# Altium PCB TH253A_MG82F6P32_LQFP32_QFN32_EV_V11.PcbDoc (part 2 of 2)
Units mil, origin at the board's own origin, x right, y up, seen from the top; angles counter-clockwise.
Board outline 3818.9 x 2637.8 mil, 2 copper layers (Top Layer, Bottom Layer); 102 components, 120 nets, 494 pads, 219 vias.
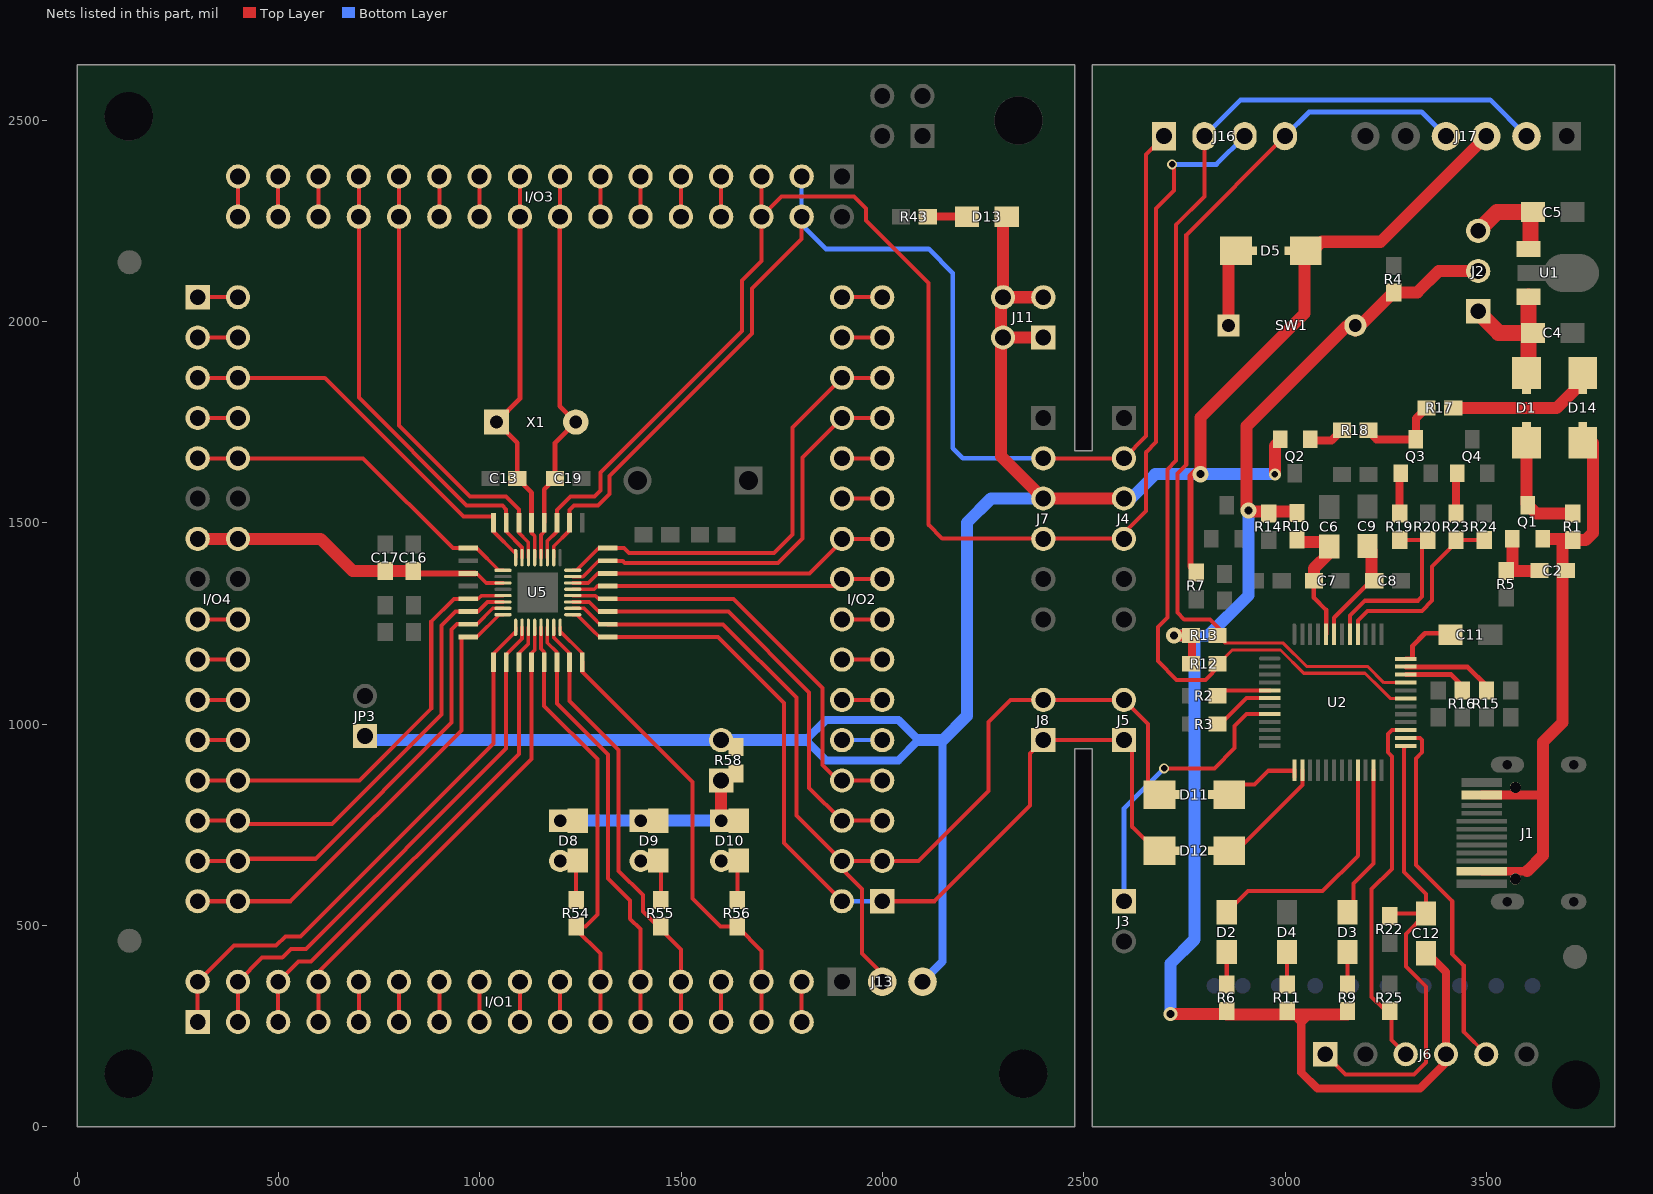
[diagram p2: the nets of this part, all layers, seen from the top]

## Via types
v1: diameter 20, hole 12, Top Layer to Bottom Layer, tented both sides, 164 vias
v2: diameter 30, hole 12, Top Layer to Bottom Layer, tented both sides, 19 vias
v3: diameter 25, hole 16, Top Layer to Bottom Layer, tented both sides, 13 vias
v4: diameter 25, hole 12, Top Layer to Bottom Layer, tented both sides, 7 vias
v5: diameter 40, hole 20, Top Layer to Bottom Layer, tented both sides, 5 vias
v6: diameter 24, hole 12, Top Layer to Bottom Layer, tented both sides, 4 vias
v7: diameter 30, hole 16, Top Layer to Bottom Layer, tented both sides, 3 vias
v8: diameter 50, hole 12, Top Layer to Bottom Layer, tented both sides, 1 vias
v9: diameter 35, hole 20, Top Layer to Bottom Layer, tented both sides, 1 vias
v10: diameter 15, hole 12, Top Layer to Bottom Layer, tented both sides, 1 vias
v11: diameter 60, hole 32, Top Layer to Bottom Layer, tented both sides, 1 vias

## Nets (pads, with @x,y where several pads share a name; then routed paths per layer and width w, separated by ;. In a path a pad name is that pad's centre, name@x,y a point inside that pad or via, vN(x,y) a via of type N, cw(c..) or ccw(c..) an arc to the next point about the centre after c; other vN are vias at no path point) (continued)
ICP/SWD_SCL: J16.2 J17.2 R12.2 U2.31 | length 2959.9
  Top Layer w8: R12.2@2844.45,1160 2868.45,1184 2988.41,1184 3046.41,1126 3198.41,1126 3238.3,1086.1 ; 3238.35,1086.1 3260.72,1063.73 U2.31@3299.91,1063.73
  Top Layer w10: J16.2@2799.45,2485 J16.2@2799.45,2460 2799.45,2310 2729.45,2240 2729.45,1654 2708.2,1632.75 2708.2,1265.05 2684.41,1241.26 2684.41,1156.26 2730.67,1110 2802.45,1110 2837.45,1145 R12.2@2842.45,1150
  Bottom Layer w12: J16.2@2799.45,2460 2889.45,2550 3509.45,2550 J17.2@3599.45,2460
ICP/SWD_SDA: J16.4 J17.4 R13.2 U2.33 | length 2399.4
  Top Layer w8: R13.2@2832.45,1220 2851.45,1201 2995.45,1201 3053.45,1143 3205.45,1143 3245.35,1103.1 U2.33@3299.91,1103.1
  Top Layer w10: R13.2@2842.45,1220 2842.45,1231 2813.45,1260 2749.45,1260 2732.2,1277.25 2732.2,1621.75 2754.45,1644 2754.45,2215 J16.4@2999.45,2460
  Bottom Layer w12: J16.4@2999.45,2460 3059.45,2520 3339.45,2520 J17.4@3399.45,2460
MLINK_RXD: D11.2 I/O2.3 I/O2.4 J5.2 J8.2 J13.2 U5.10 | length 2589.6
  Top Layer w10: U5.10@1317.25,1247.78 1317.48,1247.78 1604.07,1247.78 1786.44,1065.4 1786.44,773.01 I/O2.4@1899.45,660 I/O2.3@1999.45,660 ; I/O2.4@1899.45,640 1909.45,630 ; I/O2.4@1909.45,650 1909.45,630 ; J13.2@1999.45,360 1999.45,380 1949.45,430 1949.45,590 1909.45,630 ; I/O2.3@1999.45,650 I/O2.3@1999.45,660 ; D11.2@2659.45,810 2659.45,825 2659.45,1000 J5.2@2599.45,1060 J8.2@2399.45,1060 2317.55,1060 2263.22,1005.67 2263.22,833.77 2089.45,660 I/O2.3@1999.45,660
MLINK_TXD: D12.1 I/O2.1 I/O2.2 J5.1 J8.1 U5.9 | length 2301.3
  Top Layer w10: U5.9@1317.25,1216.28 1317.48,1216.28 1591.02,1216.28 1754.95,1052.36 1754.95,704.5 I/O2.2@1899.45,560 I/O2.2@1899.45,565 ; I/O2.1@1999.45,560 2129.45,560 2366.78,797.33 2366.78,927.33 J8.1@2399.45,960 J5.1@2599.45,960 J5.1@2605.22,954.23 ; J5.1@2619.45,958 2619.45,745 D12.1@2672.83,691.61
  Bottom Layer w10: I/O2.2@1899.45,560 I/O2.1@1999.45,560
NetC2_2: C2.2 Q1.1 R5.2 | length 170
  Top Layer w30: R5.2@3549.45,1380 R5.2@3564.45,1380 ; Q1.1@3564.45,1465 Q1.1@3564.45,1460 R5.2@3564.45,1380 ; C2.2@3634.45,1380 3631.41,1380 R5.2@3564.45,1380
NetC6_1: C6.1 C7.2 R10.2 U2.44 | length 312.7
  Top Layer w11: C7.2@3071.45,1356.26 3071.45,1313.55 3101.64,1283.36 U2.44@3101.64,1223.13 ; C7.2@3087,1356.26 C7.2@3087,1365.26
  Top Layer w30: R10.2@3044.45,1452 3109.41,1452 C6.1@3109.41,1440.79 ; C7.2@3071.45,1356.26 3071.45,1386.45 C6.1@3108,1423
NetC8_2: C8.2 C9.1 U2.43 | length 261.6
  Top Layer w11: U2.43@3121.33,1223.13 3121.33,1264.18 C8.2@3214.41,1357.26
  Top Layer w30: C9.1@3204.41,1442.05 3214.41,1432.05 C8.2@3214.41,1357.26
NetC11_1: C11.1 U2.36 | length 149.7
  Top Layer w12: U2.36@3299.91,1162.16 3316.61,1162.16 3316.61,1194.68 3347.31,1225.39 C11.1@3404.35,1225.39
NetD1_1: D1.1 Q1.3 R1.2 | length 276.4
  Top Layer w30: D1.1@3599.41,1698.39 3599.41,1546.98 Q1.3@3602.45,1543.94 3623.38,1523 R1.2@3714.45,1523
NetD2_1: D2.1 R6.2 | length 97
  Top Layer w10: R6.2@2855,345 R6.2@2855,353.26 D2.1@2855,434.05 D2.1@2855,442
NetD3_1: D3.1 R9.2 | length 97
  Top Layer w10: R9.2@3155,345 R9.2@3155,353.26 D3.1@3155,434.05 D3.1@3155,442
NetD4_1: D4.1 R11.2 | length 97
  Top Layer w10: R11.2@3005,345 R11.2@3005,353.26 D4.1@3005,434.05 D4.1@3005,442
NetD5_1: D5.1 SW1.1 | length 215.1
  Top Layer w20: D5.1@2860.28,2175 D5.1@2877.8,2175 D5.1@2911.26,2175
  Top Layer w30: SW1.1@2859.49,1990 D5.1@2859.49,2154.13
NetD8_1: D8.1 D9.1 D10.1 R58.1 | length 500
  Top Layer w30: D10.1@1599.45,760 R58.1@1599.45,860
  Bottom Layer w30: D8.1@1199.45,760 D9.1@1399.45,760 D10.1@1599.45,760
NetD8_2: D8.2 R54.2 | length 94.8
  Top Layer w10: R54.2@1239.45,563 D8.2@1239.45,657.76
NetD9_2: D9.2 R55.2 | length 92.1
  Top Layer w10: R55.2@1449.45,563 D9.2@1449.45,655.13
NetD10_2: D10.2 R56.2 | length 94.8
  Top Layer w10: R56.2@1639.45,563 D10.2@1639.45,657.76
NetD11_1: D11.1 U2.13 | length 209.6
  Top Layer w10: D11.1@2846.06,810 D11.1@2861.06,825 D11.1@2876.06,840 ; D11.1@2884.45,850 2924.45,850 2958.51,884.06 U2.13@3020.37,884.06 ; U2.13@3022.9,868.45 U2.13@3022.9,885.65
NetD12_2: D12.2 U2.14 | length 287
  Top Layer w10: D12.2@2854.45,700 2861.06,700 2894.45,700 3042.59,848.14 U2.14@3042.59,885.65
NetD13_2: D13.2 R43.2 | length 90
  Top Layer w20: R43.2@2129.45,2260 D13.2@2210.24,2260
  Top Layer w30: D13.2@2210.24,2260 D13.2@2219.45,2260
NetD14_2: D14.2 R17.1 | length 348.7
  Top Layer w30: R17.1@3417.41,1785 3669.41,1785 ; 3674.41,1785 D14.2@3733.48,1844.07 ; D14.2@3722.56,1868.15 D14.2@3734.41,1868.15 ; D14.2@3728.48,1844.07 D14.2@3729.41,1845
NetI/O1_9: I/O1.9 I/O1.10 | length 100
  Top Layer w10: I/O1.9@699.45,260 I/O1.10@699.45,360
NetI/O1_11: I/O1.11 I/O1.12 | length 100
  Top Layer w10: I/O1.11@799.45,260 I/O1.12@799.45,360
NetI/O1_13: I/O1.13 I/O1.14 | length 100
  Top Layer w10: I/O1.13@899.45,260 I/O1.14@899.45,360
NetI/O1_15: I/O1.15 I/O1.16 | length 100
  Top Layer w10: I/O1.15@999.45,260 I/O1.16@999.45,360
NetI/O1_17: I/O1.17 I/O1.18 | length 116.7
  Top Layer w10: I/O1.18@1087.63,371.82 I/O1.18@1099.45,360 I/O1.17@1099.45,260
NetI/O1_19: I/O1.19 I/O1.20 | length 100
  Top Layer w10: I/O1.19@1199.45,260 I/O1.20@1199.45,360
NetI/O1_27: I/O1.27 I/O1.28 | length 112.4
  Top Layer w10: I/O1.28@1595.19,360 1595.19,355.74 I/O1.28@1599.45,351.48 ; I/O1.27@1599.45,260 I/O1.28@1599.45,351.48 ; I/O1.28@1599.45,360 I/O1.28@1599.45,351.48 ; I/O1.28@1600.93,350 I/O1.28@1599.45,351.48
NetI/O1_31: I/O1.31 I/O1.32 | length 100
  Top Layer w10: I/O1.31@1799.45,260 I/O1.32@1799.45,360
NetI/O2_9: I/O2.9 I/O2.10 | length 100
  Bottom Layer w10: I/O2.10@1899.45,960 I/O2.9@1999.45,960
NetI/O2_11: I/O2.11 I/O2.12 | length 100
  Top Layer w10: I/O2.12@1899.45,1060 I/O2.11@1999.45,1060
NetI/O2_13: I/O2.13 I/O2.14 | length 100
  Top Layer w10: I/O2.14@1899.45,1160 I/O2.13@1999.45,1160
NetI/O2_15: I/O2.15 I/O2.16 | length 100
  Top Layer w10: I/O2.16@1899.45,1260 I/O2.15@1999.45,1260
NetI/O2_21: I/O2.21 I/O2.22 | length 100
  Top Layer w10: I/O2.22@1899.45,1560 I/O2.21@1999.45,1560
NetI/O2_23: I/O2.23 I/O2.24 | length 100
  Top Layer w10: I/O2.24@1899.45,1660 I/O2.23@1999.45,1660
NetI/O2_29: I/O2.29 I/O2.30 | length 100
  Top Layer w10: I/O2.30@1899.45,1960 I/O2.29@1999.45,1960
NetI/O2_31: I/O2.31 I/O2.32 | length 100
  Top Layer w10: I/O2.32@1899.45,2060 I/O2.31@1999.45,2060
NetI/O3_7: I/O3.7 I/O3.8 | length 100
  Top Layer w10: I/O3.8@1599.45,2260 I/O3.7@1599.45,2360
NetI/O3_9: I/O3.9 I/O3.10 | length 100
  Top Layer w10: I/O3.10@1499.45,2260 I/O3.9@1499.45,2360
NetI/O3_11: I/O3.11 I/O3.12 | length 100
  Top Layer w10: I/O3.12@1399.45,2260 I/O3.11@1399.45,2360
NetI/O3_13: I/O3.13 I/O3.14 | length 100
  Top Layer w10: I/O3.14@1299.45,2260 I/O3.13@1299.45,2360
NetI/O3_19: I/O3.19 I/O3.20 | length 100
  Top Layer w10: I/O3.20@999.45,2260 I/O3.19@999.45,2360
NetI/O3_21: I/O3.21 I/O3.22 | length 100
  Top Layer w10: I/O3.22@899.45,2260 I/O3.21@899.45,2360
NetI/O3_27: I/O3.27 I/O3.28 | length 100
  Top Layer w10: I/O3.28@599.45,2260 I/O3.27@599.45,2360
NetI/O3_29: I/O3.29 I/O3.30 | length 100
  Top Layer w10: I/O3.30@499.45,2260 I/O3.29@499.45,2360
NetI/O3_31: I/O3.31 I/O3.32 | length 100
  Top Layer w10: I/O3.32@399.45,2260 I/O3.31@399.45,2360
NetI/O4_1: I/O4.1 I/O4.2 | length 123.5
  Top Layer w10: I/O4.1@299.45,2060 I/O4.2@399.45,2060 I/O4.2@399.45,2036.48
NetI/O4_3: I/O4.3 I/O4.4 | length 100
  Top Layer w10: I/O4.3@299.45,1960 I/O4.4@399.45,1960
NetI/O4_7: I/O4.7 I/O4.8 | length 100
  Top Layer w10: I/O4.7@299.45,1760 I/O4.8@399.45,1760
NetI/O4_17: I/O4.17 I/O4.18 | length 100
  Top Layer w10: I/O4.17@299.45,1260 I/O4.18@399.45,1260
NetI/O4_19: I/O4.19 I/O4.20 | length 100
  Top Layer w10: I/O4.19@299.45,1160 I/O4.20@399.45,1160
NetI/O4_21: I/O4.21 I/O4.22 | length 100
  Top Layer w10: I/O4.21@299.45,1060 I/O4.22@399.45,1060
NetI/O4_23: I/O4.23 I/O4.24 | length 100
  Top Layer w10: I/O4.23@299.45,960 I/O4.24@399.45,960
NetQ2_1: Q2.1 R18.2 | length 89.8
  Top Layer w20: Q2.1@3062.41,1703.94 3115.38,1703.94 R18.2@3141.45,1730
NetQ3_1: Q3.1 R19.2 | length 117.1
  Top Layer w20: R19.2@3284.45,1540.04 R19.2@3284.45,1523 Q3.1@3284.45,1620.53 ; Q3.1@3286.95,1620.53 Q3.1@3286.95,1623.03
NetQ3_2: Q3.2 R17.2 R18.1 | length 192.7
  Top Layer w20: R18.1@3212.45,1730 3212.45,1721.96 3227.44,1706.97 Q3.2@3324.95,1706.97 ; 3324.95,1730 3324.95,1758.54 R17.2@3351.41,1785
NetQ4_1: Q4.1 R23.2 | length 100
  Top Layer w20: R23.2@3424.45,1523 Q4.1@3424.45,1620.53 ; Q4.1@3426.95,1620.53 Q4.1@3426.95,1623.03
NetR15_1: R15.1 U2.35 | length 263.6
  Top Layer w12: U2.35@3299.91,1141.47 3329.45,1141.47 ; 3361.71,1141.47 3329.45,1141.47 ; R15.1@3500,1083 3500,1095 3453.53,1141.47 3329.45,1141.47
NetR16_1: R16.1 U2.34 | length 163.6
  Top Layer w12: U2.34@3299.91,1122.79 3412.21,1122.79 3440,1095 R16.1@3440,1083
OCD_CLK/P44: I/O3.3 I/O3.4 J4.2 J7.2 J16.1 U5.18 | length 3313.6
  Top Layer w10: U5.18@1222.99,1498 U5.18@1222.99,1500 1222.99,1531.88 1234.11,1543 1294.11,1543 1322,1570.89 1322,1616.07 1675.93,1970 1675.93,2081.48 1799.45,2205 I/O3.4@1799.45,2260 ; J7.2@2399.45,1659 J4.2@2599.45,1659 ; J4.2@2599.45,1660 2654.45,1715 2654.45,2415 J16.1@2699.45,2460
  Bottom Layer w10: I/O3.4@1799.45,2240 I/O3.4@1799.45,2260 I/O3.3@1799.45,2360
  Bottom Layer w12: I/O3.4@1799.45,2240 1859.45,2180 2114.45,2180 2174.45,2120 2174.45,1685 2199.45,1660 J7.2@2399.45,1660 J7.2@2384.45,1675
OCD_SDA/P45: I/O3.5 I/O3.6 J4.4 J7.4 J16.3 U5.19 | length 3920.1
  Top Layer w10: U5.19@1191.5,1500 1191.5,1531.5 1225,1565 1285,1565 1300,1580 1300,1625.18 1650.93,1976.11 1650.93,2101.48 1699.45,2150 I/O3.6@1699.45,2260 ; I/O3.5@1699.45,2360 I/O3.6@1699.45,2260 ; J7.4@2399.45,1460 2398.45,1461 2148.45,1461 2114.45,1495 2114.45,2095 1959.45,2250 1959.45,2280 1929.45,2310 1749.45,2310 I/O3.6@1699.45,2260 ; J7.4@2399.45,1461 J4.4@2585.45,1461 ; J4.4@2592.45,1467 2654.45,1529 2654.45,1675 2679.45,1700 2679.45,2280 2724.45,2325 v3@2724.45,2390
  Bottom Layer w12: v3(2719.45,2390) 2829.45,2390 J16.3@2899.45,2460
P01: I/O3.23 I/O3.24 U5.22 | length 1040.2
  Top Layer w10: I/O3.23@799.45,2360 I/O3.24@799.45,2260 799.45,1741.8 976.25,1565 1065,1565 1097.01,1532.99 U5.22@1097.01,1500 U5.22@1097.01,1495
P02: I/O3.25 I/O3.26 U5.23 | length 1065.6
  Top Layer w10: I/O3.25@699.45,2360 I/O3.26@699.45,2260 699.45,1810.69 967.14,1543 1055.89,1543 1065.51,1533.38 U5.23@1065.51,1500 U5.23@1065.51,1498
P05: I/O4.5 I/O4.6 U5.24 | length 892.6
  Top Layer w10: I/O4.5@299.45,1860 I/O4.6@399.45,1860 ; I/O4.6@409.45,1850 I/O4.6@399.45,1860 ; U5.24@1035,1515 1034.02,1515 960,1515 615,1860 I/O4.6@399.45,1860
P07: I/O4.9 I/O4.10 U5.25 | length 763.9
  Top Layer w10: I/O4.9@299.45,1660 I/O4.10@399.45,1660 710,1660 932.99,1437.01 U5.25@971.02,1437.01
P10: I/O4.25 I/O4.26 U5.29 | length 984.9
  Top Layer w10: I/O4.25@299.45,860 I/O4.26@399.45,860 700.93,860 879.45,1038.52 879.45,1254.45 936.02,1311.02 U5.29@971.02,1311.02
P11: I/O4.27 I/O4.28 U5.30 | length 1033
  Top Layer w10: I/O4.27@299.45,760 I/O4.28@399.45,760 ; I/O4.28@389.45,760 I/O4.28@399.45,760 ; U5.30@971.02,1279.53 939.53,1279.53 904.45,1244.45 904.45,1023.52 632.69,751.76 407.69,751.76 I/O4.28@399.45,760
P12: I/O4.29 I/O4.30 U5.31 | length 1050.4
  Top Layer w10: I/O4.29@299.45,660 I/O4.30@399.45,660 404.94,665.49 591.42,665.49 929.45,1003.52 929.45,1234.45 943.03,1248.03 U5.31@971.02,1248.03
P13: I/O4.31 I/O4.32 U5.32 | length 1061.9
  Top Layer w10: I/O4.31@299.45,560 I/O4.32@399.45,560 530.47,560 955,984.53 U5.32@955,1215
P14: I/O1.1 I/O1.2 U5.1 | length 1281.3
  Top Layer w10: I/O1.1@299.45,260 I/O1.2@299.45,360 389.45,450 494.45,450 517.44,472.99 555,472.99 1034.02,952.01 U5.1@1034.02,1153.54
P15: I/O1.3 I/O1.4 U5.2 | length 1220.5
  Top Layer w10: I/O1.3@399.45,260 I/O1.4@399.45,360 459.45,420 509.45,420 530.94,441.5 568.04,441.5 1065.51,938.97 U5.2@1065.51,1153.54
P16: I/O1.5 I/O1.6 U5.3 | length 1159.6
  Top Layer w10: I/O1.5@499.45,260 I/O1.6@499.45,360 549.45,410 581.09,410 1097.01,925.92 U5.3@1097.01,1153.54
P17: I/O1.7 I/O1.8 U5.4 | length 1112.7
  Top Layer w10: I/O1.7@599.45,260 I/O1.8@599.45,360 599.45,383.82 1128.5,912.87 U5.4@1128.5,1153.54
P22: I/O1.21 I/O1.22 R54.1 U5.5 | length 998.1
  Top Layer w10: U5.5@1160,1153.54 1160,1045.06 1292.01,913.05 1292.01,527.01 1262,497 R54.1@1239.45,497 1239.45,490 1299.45,430 I/O1.22@1299.45,370 ; I/O1.21@1299.45,260 I/O1.22@1299.45,360
P23: I/O1.23 I/O1.24 U5.6 | length 989.6
  Top Layer w10: U5.6@1191.5,1153.54 1191.5,1051.03 1318.5,924.03 1318.5,616.95 1373.5,561.95 1373.5,516.5 1399.35,490.65 1399.35,360 I/O1.24@1399.35,350 ; I/O1.23@1399.45,260 I/O1.24@1399.45,360
P24: I/O1.25 I/O1.26 R55.1 U5.7 | length 1041.1
  Top Layer w9: 1222.99,1122.01 U5.7@1222.99,1153.54
  Top Layer w10: U5.7@1222.99,1150 1222.99,1057.01 1345,935 1345,635 1405,575 1405,534.45 1445.95,493.5 R55.1@1449.45,490 ; R55.1@1449.45,497 R55.1@1449.45,490 ; I/O1.25@1499.45,260 I/O1.26@1499.45,360 ; I/O1.26@1499.45,361.9 1499.45,440 R55.1@1449.45,490
P26: I/O1.29 I/O1.30 R56.1 U5.8 | length 1102.5
  Top Layer w10: U5.8@1254.35,1130 U5.8@1254.49,1129.86 ; U5.8@1254.49,1153.54 U5.8@1254.49,1129.86 ; 1528.1,856.25 U5.8@1254.49,1129.86 ; 1528.24,856.11 1528.24,566.21 1576.62,517.82 1597.45,497 R56.1@1639.45,497 1699.45,437 I/O1.30@1699.45,360 I/O1.29@1699.45,260
P32: I/O2.5 I/O2.6 U5.11 | length 1036.1
  Top Layer w10: U5.11@1317.25,1279.28 1317.48,1279.28 1617.11,1279.28 1817.94,1078.45 1817.94,841.51 I/O2.6@1899.45,760 I/O2.5@1999.45,760
P33: I/O2.7 I/O2.8 U5.12 | length 981.1
  Top Layer w10: U5.12@1317.25,1310.77 1317.48,1310.77 1630.16,1310.77 1850.93,1090 1850.93,898.52 1889.45,860 I/O2.8@1899.45,860 I/O2.7@1999.45,860
P34: I/O2.17 I/O2.18 U5.13 | length 713.7
  Top Layer w10: 1292.96,1342.52 U5.13@1317.48,1342.52 1892.52,1342.52 1904.72,1354.72 1910,1360 I/O2.17@1999.45,1360
P35: I/O2.19 I/O2.20 U5.14 | length 729.4
  Top Layer w10: U5.14@1317.48,1374.02 1818.46,1374.02 1896.95,1452.5 1899.45,1452.5 1906.95,1452.5 I/O2.20@1912.2,1457.76 ; I/O2.20@1899.45,1460 I/O2.19@1999.45,1460
P40: I/O2.25 I/O2.26 U5.15 | length 943.7
  Top Layer w10: U5.15@1325,1405 1355,1405 1360,1400 1740.93,1400 1801.18,1460.25 1801.18,1661.73 I/O2.26@1899.45,1760 I/O2.25@1999.45,1760
P41: I/O2.27 I/O2.28 U5.16 | length 1036.9
  Top Layer w10: U5.16@1317.48,1437.01 1357.99,1437.01 1370,1425 1730.93,1425 1776.43,1470.5 1776.43,1736.98 I/O2.28@1899.45,1860 ; I/O2.28@1885.82,1860 I/O2.28@1899.45,1860 ; I/O2.27@1999.45,1860 I/O2.28@1899.45,1860
P44: J6.5 U2.26 | length 900.8
  Top Layer w10: U2.26@3299.91,965.31 3334.69,965.31 3340,960 3340,930 3325,915 3325,650 3415,560 3415,429 3443.55,400.45 3443.55,235.9 J6.5@3499.45,180
P45: J6.3 R25.1 U2.27 | length 924.9
  Top Layer w10: R25.1@3263.72,290.72 3263.72,287 3263.72,215.72 J6.3@3299.45,180 ; R25.1@3265,292 3260,292 3245.44,292 3215,322.44 3215,590 3265,640 3265,920 3255,930 3255,975 3264.99,984.99 U2.27@3299.91,984.99 ; J6.3@3300.72,181.28 J6.3@3308,174
PASS: D3.2 U2.23 | length 376.3
  Top Layer w10: D3.2@3170,530 3170,532.47 3170,604.16 3219.75,653.92 U2.23@3219.75,885.65
RST: C12.2 J6.1 R22.2 U2.25 | length 1228.1
  Top Layer w10: J6.1@3099.45,180 3149.45,130 3320,130 3350,160 3350,348 3300,398 3300,479.21 C12.2@3350,529.21 ; R22.2@3266.21,529.21 C12.2@3350,529.21 ; U2.25@3300,945 3295,940 3295,633 3350,578 C12.2@3350,529.21 ; U2.25@3309.45,945.62 U2.25@3318.83,945.62
RST_CTRL_51: R19.1 R20.1 U2.41 | length 455
  Top Layer w10: U2.41@3160.7,1223.13 3160.7,1269.12 3197.83,1306.26 3329.41,1306.26 3339.45,1316.3 R20.1@3339.45,1457 ; R19.1@3284.45,1457 R20.1@3339.45,1457 ; R20.1@3354.45,1457 R20.1@3339.45,1457
RST_CTRL_ARM: R23.1 R24.1 U2.40 | length 474.6
  Top Layer w10: U2.40@3180.38,1223.13 3180.38,1256.93 3204.71,1281.26 3339.41,1281.26 3364.45,1306.3 3364.45,1391.3 R23.1@3421.91,1448.76 ; R23.1@3424.45,1457 R24.1@3494.45,1457
TOOL_OPTION0: R2.1 U2.5 | length 135.2
  Top Layer w10: R2.1@2832.45,1070 2846.37,1083.92 U2.5@2961.93,1083.92
TOOL_OPTION1: R3.1 U2.6 | length 156.1
  Top Layer w10: R3.1@2832.45,1000 2839.45,1000 2903.68,1064.23 U2.6@2961.93,1064.23
USBOK: D2.2 U2.21 | length 596.3
  Top Layer w10: D2.2@2855,532.47 2907.53,585 3092.45,585 3180.38,672.94 U2.21@3180.38,885.65
VCAP: C16.1 C17.1 I/O4.13 I/O4.14 U5.27 | length 768.9
  Top Layer w15: C16.1@835,1374.02 U5.27@971.02,1374.02 U5.27@987.76,1374.02
  Top Layer w30: I/O4.13@299.45,1460 I/O4.14@399.45,1460 604.45,1460 642.22,1422.22 ; 620,1444.45 642.22,1422.22 ; 805.98,1380 790,1380 ; C16.1@835,1380 790,1380 ; 642.22,1422.22 684.45,1380 C17.1@765,1380 790,1380
VCC_USB: C2.1 D14.1 J1.A4 J1.A9 J1.M5 J1.M6 Q1.2 R1.1 | length 1456.2
  Top Layer w22: J1.A4@3488.25,634.61 3571.65,634.61 3601.07,634.61 ; J1.A9@3488.25,823.62 3571.65,823.62 3640,823.62
  Top Layer w30: 3601.07,634.61 3640,673.54 3640,823.62 3640,955 3689.33,1004.33 3689.33,1381.26 3689.33,1446.88 ; Q1.2@3639.45,1460 3691.45,1460 ; R1.1@3704.45,1457 R1.1@3714.45,1457 3746.41,1457 3764.41,1475 D14.1@3764.41,1698.39
VCP_OPTION: J3.1 U2.8 | length 722
  Top Layer w10: v3(2699.41,890) 2824.45,890 2874.45,940 2874.45,995 2904.31,1024.86 U2.8@2961.93,1024.86
  Bottom Layer w12: J3.1@2599.45,560 2599.45,790.04 v3(2699.41,890)
VDD: C12.1 J2.2 J6.4 R4.1 R6.1 R9.1 R10.1 R11.1 R12.1 R13.1 R14.2 SW1.2 | length 3958.9
  Top Layer w12: R11.1@3014.19,279.52 3014.71,279 3040,253.71 3040.35,253.36 ; 3040.36,251.65 3066.52,277.81
  Top Layer w20: v5@2727.52,1215 R13.1@2761.45,1215 ; v5@2732.52,1225 R13.1@2766.45,1225 ; R12.1@2768.45,1150 R13.1@2768.45,1219.56 ; 3040,279 3040,253.71 3040,135 3080,95 3335,95 3399.45,159.45 J6.4@3399.45,180 3399.45,384.55 3360,424 C12.1@3360,430.79
  Top Layer w30: v9(2715,280) R6.1@2855,280 ; R6.1@2855,279 3005,279 3014.71,279 3040,279 R9.1@3155,279 ; R14.2@2964.41,1528 2959.41,1528 2911.41,1528 v5(2909.41,1530) 2904.41,1535 2904.41,1740 3153.16,1988.75 3163.24,1988.75 3168.22,1983.77 3174.45,1977.54 3180.68,1983.77 3268.91,2072 R4.1@3269.45,2072 3328.41,2072 3381.41,2125 J2.2@3479.45,2125 ; R14.2@2969.41,1528 R10.1@3029.41,1528
  Bottom Layer w30: v9(2715,280) 2715,405 2775,465 2775,1220 ; v5(2724.45,1220) 2775,1220 ; 2775,1220.1 2775,1220 ; v5(2909.41,1530) 2909.41,1319.96 2809.45,1220 2775,1220
VDD3: C5.1 J2.3 U1.1 | length 231.2
  Top Layer w40: J2.3@3479.45,2225 3525.71,2271.26 C5.1@3609.41,2271.26 ; U1.1@3609.41,2195 C5.1@3609.41,2271.26 ; C5.1@3615.2,2271.26 C5.1@3609.41,2271.26
VDD5: C4.1 D1.2 J2.1 U1.3 | length 318.5
  Top Layer w40: J2.1@3477.97,2023.52 3530.24,1971.26 C4.1@3604.41,1971.26 ; D1.2@3604.41,1901.61 C4.1@3604.41,1971.26 ; U1.3@3604.41,2061.26 C4.1@3604.41,1971.26 ; C4.1@3615.2,1971.26 C4.1@3604.41,1971.26
VDUT: D5.2 D13.1 J4.3 J7.3 J11.1 J11.2 J11.3 J11.4 J13.3 J17.3 JP3.1 Q2.2 R7.1 R58.2 | length 6571.2
  Top Layer w15: R7.1@2779.45,1376 2764.45,1391 2764.45,1615.5 2779.45,1630.5 2789.45,1640.5 ; v5@2797.2,1612.75 v5@2799.45,1615
  Top Layer w20: D5.2@3017.56,2175 D5.2@3051.02,2175 D5.2@3068.54,2175
  Top Layer w30: J11.4@2294.45,2060 2294.45,1960 2294.45,1665 J7.3@2399.45,1560 J4.3@2599.45,1560 ; J11.2@2299.45,1960 J11.1@2399.45,1960 ; J11.4@2299.45,2060 D13.1@2299.45,2250.79 ; J11.4@2309.45,2060 J11.3@2399.45,2060 J11.3@2409.45,2060 ; v5(2789.45,1620.5) 2789.45,1640.5 2789.45,1760.91 3048.54,2020 D5.2@3048.54,2170 ; v7@2974.41,1620.5 2974.41,1690.94 Q2.2@2987.41,1703.94 ; D5.2@3063.54,2170 3068.54,2175 3091.3,2197.76 3237.21,2197.76 J17.3@3499.45,2460
  Bottom Layer w20: J13.3@2099.45,360 2149.45,410 2149.45,960 ; 1809.45,960 1859.45,1010 2039.45,1010 2089.45,960 2039.45,910 1859.45,910 1809.45,960
  Bottom Layer w30: JP3.1@715,960 1120,960 ; 899.45,960 1120,960 ; 1809.45,960 R58.2@1599.45,960 1120,960 ; 2089.45,960 2149.45,960 2209.45,1020 2209.45,1500 2269.45,1560 J7.3@2399.45,1560 ; J4.3@2617.48,1560.5 2677.48,1620.5 v5(2789.45,1620.5) v7@2974.41,1620.5
  other v7: 2974.41,1620
XIN/P61: C19.1 I/O3.15 I/O3.16 U5.20 X1.2 | length 910.7
  Top Layer w10: I/O3.16@1199.45,2260 I/O3.15@1199.45,2360
  Top Layer w12: U5.20@1160,1500 1160,1583 C19.1@1187,1610 1187,1698.58 X1.2@1238.43,1750 1198.74,1789.68 1198.74,2260 I/O3.16@1198.74,2261.79
XOUT/P60: C13.1 I/O3.17 I/O3.18 U5.21 X1.1 | length 920
  Top Layer w10: I/O3.18@1099.45,2260 I/O3.17@1099.45,2360
  Top Layer w12: I/O3.18@1099.45,2260 1099.45,1807.87 X1.1@1041.58,1750 1093,1698.58 C13.1@1093,1610 1128.5,1574.5 U5.21@1128.5,1500
pads on no net: J1.A5 J1.A8 J1.B5 J1.B8 J6.6 J7.1 U2.1 U2.2 U2.3 U2.4 U2.7 U2.24 U2.28 U2.29 U2.30 U2.32 U2.37 U2.38 U2.39 U2.46

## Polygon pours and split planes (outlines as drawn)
GND_POWER on Bottom Layer "Top Layer-No Net" (hatched 90Degree grid 10 track 10, remove dead copper, pour order 1001): 29.45,30 3789.45,30 3789.45,2610 29.45,2610
GND_POWER on Top Layer "Top Layer-No Net" (hatched 90Degree grid 10 track 10, remove dead copper, pour order 1001): 29.45,30 3789.45,30 3789.45,2610 29.45,2610

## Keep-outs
Top Layer:
  circle w5: c130,2146.9 r59.06
  circle w5: c130,461.9 r59.06
  circle w5: c3720,421.9 r59.06
Keep-Out Layer:
  lines w7.88: 27.88,201.48 cw(c128.35,131.26) 205.29,35.84 ; 32.93,2432.11 ccw(c128.35,2509.06) 198.57,2609.52 ; 2260.85,2594.47 ccw(c2337.8,2499.06) 2438.26,2428.83 ; 2279.23,30.79 cw(c2349.45,131.26) 2444.87,208.2
  lines w15: 3818.9,1.26 3818.9,2639.06

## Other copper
Top Layer:
  pour cut-out: 2439.45,2639.06 2559.45,2639.06 2559.45,0 2439.45,0
Bottom Layer:
  pour cut-out: 2439.45,2639.06 2559.45,2639.06 2559.45,0 2439.45,0

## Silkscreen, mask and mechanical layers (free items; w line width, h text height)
Top Overlay:
  circle w5: c2337.8,2499.06 r120
  circle w5: c2349.45,131.26 r120
  circle w5: c128.35,131.26 r120
  circle w5: c128.35,2509.06 r120
  region: 2601.52,264.05 2627.17,335.95 2611.52,334.05 2611.52,394.05 2591.52,394.05 2591.52,334.05 2577.17,335.95
  region: 1999.45,450 2009.45,450 2009.45,420 2019.45,420 2004.45,405 1989.45,420 1999.45,420
  text "GND" at 1789.45,2560 h50
  text "P02" at 724.45,2425 h40 r90
  text "P01" at 824.45,2425 h40 r90
  text "P60" at 1070,2425 h40 r90
  text "X_OUT" at 1120,2425 h40 r90
  text "P61" at 1205,2425 h40 r90
  text "X_IN" at 1255,2425 h40 r90
  text "P45" at 1724.45,2425 h40 r90
  text "P44" at 1824.45,2425 h40 r90
  text "RST" at 1924.45,2425 h40 r90
  text "When J16 Open," at 2564.45,2335 h45
  text "Power" at 2149.45,2320 h50
  text "SCL" at 3619.45,2320 h35 r90
  text "CLK" at 3719.45,2320 h35 r90
  text "RST" at 3219.45,2310 h37 r90
  text "GND" at 3319.45,2305 h37 r90
  text "SDA" at 3419.45,2305 h37 r90
  text "VCC" at 3519.45,2305 h37 r90
  text "SW1 must be off." at 2564.45,2260 h45
  text "VDD3" at 3289.41,2201.9 h37
  text "VDUT" at 2249.45,2130 h50
  text "VDD" at 3319.45,2105 h37
  text "VDD5" at 3289.41,1991.9 h37
  text "2024.02" at 1439.45,1990 h40
  text "TH253A" at 479.45,1980 h60
  text "MG82F6P32_LQFP32_QFN32_EV_V11" at 489.45,1890 h50
  text "Power On" at 3099.45,1845 h45
  text "P05" at 129.45,1840 h40
  text "P41" at 2059.45,1840 h40
  text "Power Off" at 2669.45,1840 h45
  text "P40" at 2059.45,1740 h40
  text "RESET" at 1419.45,1720 h50
  text "P07" at 129.45,1640 h40
  text "SCL" at 2239.45,1640 h35
  text "GND" at 129.45,1540 h40
  text "VDUT" at 2209.45,1540 h35
  text "Vcap" at 104.45,1440 h40
  text "P35" at 2059.45,1440 h40
  text "SDA" at 2239.45,1440 h35
  text "VDD" at 129.45,1340 h40
  text "P34" at 2059.45,1340 h40
  text "GND" at 2239.45,1340 h35
  text "RST" at 2239.45,1240 h35
  text "↓" at 2329.45,1090 h110 r90
  text "↓" at 2719.45,1060 h100 r90
  text "P31_TX" at 2139.45,1040 h37
  text "↓" at 2669.45,960 h100 r270
  text "P30_RX" at 2139.45,950 h37
  text "↓" at 2279.45,930 h110 r270
  text "U5 current" at 580.93,865 h45 r90
  text "measurement" at 640.93,860 h40 r90
  text "P10" at 129.45,840 h40
  text "P33" at 2059.45,840 h40
  text "P11" at 129.45,740 h40
  text "P32" at 2059.45,740 h40
  text "P12" at 129.45,640 h40
  text "P31" at 2059.45,640 h40
  text "P13" at 129.45,540 h40
  text "P30" at 2059.45,540 h40
  text "P31_TX" at 1929.45,460 h37
  text "GND" at 1859.45,410 h35
  text "VDD" at 2099.45,410 h35
  text "ISP" at 2169.45,310 h50
  text "J3" at 2559.45,201.9 h45
  text "Open Disable VCP." at 2540,130 h40
  text "P14" at 324.45,100 h40 r90
  text "P15" at 424.45,100 h40 r90
  text "P16" at 524.45,100 h40 r90
  text "P17" at 624.45,100 h40 r90
  text "P22" at 1324.45,100 h40 r90
  text "P23" at 1424.45,100 h40 r90
  text "P24" at 1524.45,100 h40 r90
  text "P26" at 1719.45,100 h40 r90
  text "Short Enable VCP." at 2540,35 h40
Mechanical 1:
  circle w7.88: c2499.45,1615 r27
  circle w7.88: c2499.45,1505 r27
  circle w7.88: c2499.45,1418 r25
  circle w7.88: c2499.45,1300 r25
  circle w7.88: c2499.45,1010 r33
  lines w7.88: 2477.8,1080 2477.8,1234 2521.1,1234 2521.1,1080 2477.8,1080
  lines w8.88: 0,0 2477.8,0 2477.8,938.74 2521.1,938.74 2521.1,0 3818.9,0 3818.9,2637.8 2521.1,2637.8 2521.1,1678.74 2477.8,1678.74 2477.8,2637.8 0,2637.8 0,0
Mechanical 2:
  lines w6: 2499.45,1033 2499.45,1010 2522.45,1010 ; 2499.45,1323 2499.45,1300 2522.45,1300 ; 2499.45,1443 2499.45,1420 2522.45,1420 ; 2499.45,1528 2499.45,1505 2522.45,1505 ; 2499.45,1638 2499.45,1615 2522.45,1615

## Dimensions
0,0 to 3818.9,0 on Top Overlay
0,0 to 0,2637.8 on Top Overlay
